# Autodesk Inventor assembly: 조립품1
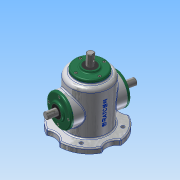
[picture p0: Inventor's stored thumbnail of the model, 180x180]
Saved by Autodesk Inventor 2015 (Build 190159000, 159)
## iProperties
Created: 2022-04
Part Number: 조립품1
Document SubType Name: Assembly
Designer: User
Author: User
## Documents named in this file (19)
- C:\Users\User\Desktop\720406V1006\조립품1.iam
- C:\Users\User\Desktop\720406V1006\본체.ipt
- C:\Users\User\Desktop\720406V1006\베어링 6203.ipt
- C:\Users\User\Desktop\720406V1006\커버.ipt
- C:\Users\User\Desktop\720406V1006\볼트 M4.ipt
- 볼트 M4.ipt
- C:\Users\User\Desktop\720406V1006\메인 축.ipt
- 메인 축.ipt
- C:\Users\User\Desktop\720406V1006\서브 축.ipt
- 서브 축.ipt
- C:\Users\User\Desktop\720406V1006\키 5x5.ipt
- C:\Users\User\Desktop\720406V1006\키 4x4.ipt
- C:\Users\User\Desktop\720406V1006\메인 베벨기어.ipt
- C:\Users\User\Desktop\720406V1006\서브 베벨기어.ipt
- C:\Users\User\Desktop\720406V1006\메인 축_MIR.ipt
- C:\Users\User\Desktop\720406V1006\키 5x5_MIR.ipt
- C:\Users\User\Desktop\720406V1006\메인 베벨기어_MIR.ipt
- C:\Users\User\Desktop\720406V1006\오일 실.ipt
- 오일 실.ipt
